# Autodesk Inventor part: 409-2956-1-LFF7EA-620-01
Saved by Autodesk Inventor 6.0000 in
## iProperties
Created: 2010-06
Part Number: 409-2956-1-LFF7EA-620-01
Cost Center: 0 lbmass
Material: A36 STEEL PLATE
Document SubType Name: Sheet Metal
Designer: S. Boerckel
Authority: 0 in^3
Mass: 6349.33 g
Surface Area: 1025.28 cm^2
Volume: 807.803 cm^3
Density: 7.86 g/cm^3
Flat Pattern Width: 15.24 cm
Flat Pattern Length: 27.94 cm
Flat Pattern Area: 425.806 cm^2
Sheet Metal Rule: 3/4"Thk
Sheet Metal Width: 11.0000 in
Sheet Metal Length: 66.0000 in^2
Description: STRAINER MOUNT PLATE
User Status: BURN
SaveDate: 2008-01-15
SaveTime: 10:24
FileName: Sheet Metal
Wide: =<Flat Pattern Width>cm
Length: =<Flat Pattern Length>cm
Thickness: 0.7500 in
SMR: =<Sheet Metal Rule> - <Material>
Author: S. Boerckel
Revision Number: A
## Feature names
1. Hole1
2. Plate1
